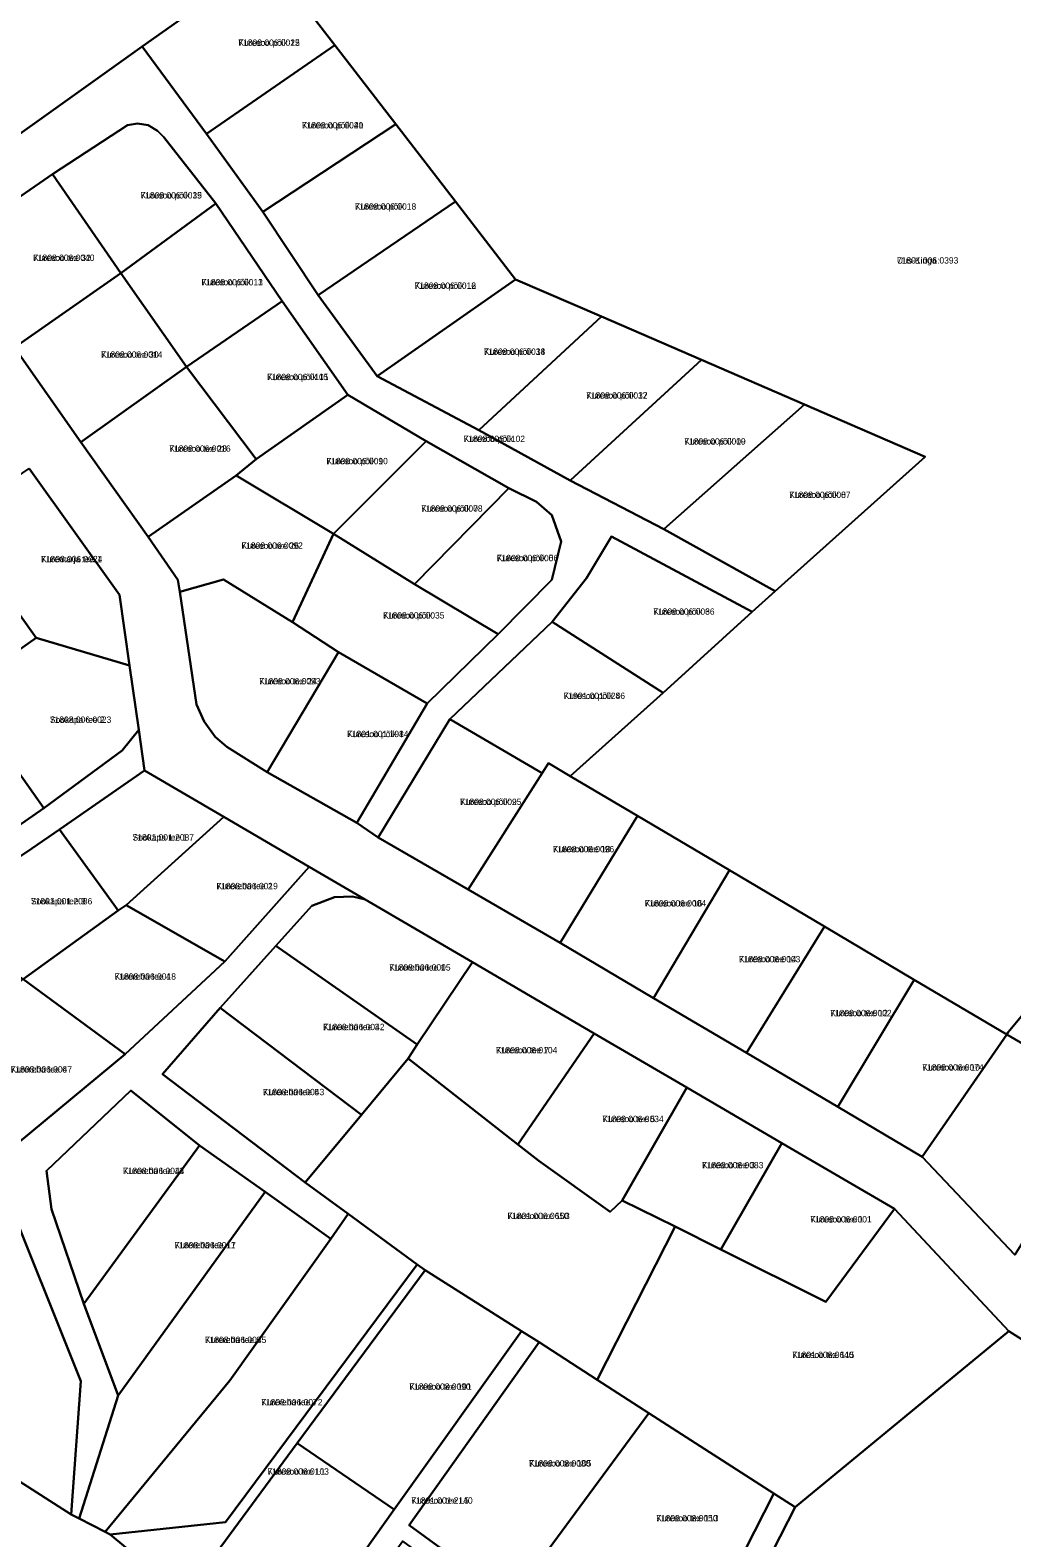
# Model space of a CAD drawing. Extents: x 529768 to 552006, y 6562269 to 6580975.
# Drawn here: x 537239.9 to 537471.9, y 6569320.5 to 6569676.9 of the extents above; entities that cross this region are included whole.
import ezdxf

# ---------------------------------------------------------------- set-up
doc = ezdxf.new("R2010")
doc.units = 0
for name, color, linetype in [('L_AADRESS', 7, 'Continuous'), ('PIIR', 7, 'Continuous'), ('TUNNUS', 7, 'Continuous')]:
    doc.layers.add(name, color=color, linetype=linetype)

msp = doc.modelspace()

# ---------------------------------------------------------------- linework, layer by layer
at = {"layer": 'PIIR'}
for points in [[(537474.6, 6569444.23), (537471.03, 6569440), (537470.72, 6569439.43), (537448.83, 6569452.41), (537427.63, 6569464.97), (537405.17, 6569478.28), (537383.46, 6569491.15), (537367.54, 6569500.54), (537389.48, 6569520.19), (537410.56, 6569539.41), (537415.96, 6569544.24), (537451.44, 6569576.02), (537422.94, 6569588.37), (537398.57, 6569598.92), (537374.91, 6569609.17), (537354.6, 6569617.97), (537340.43, 6569636.35), (537326.34, 6569654.65), (537311.93, 6569673.34), (537296.01, 6569694.01), (537266.4, 6569673.05), (537213.13, 6569635.04)], [(537213.13, 6569635.04), (537266.4, 6569673.05), (537281.57, 6569652.34), (537294.93, 6569633.97), (537308.02, 6569614.26), (537321.92, 6569595.11), (537345.94, 6569582.3), (537367.5, 6569570.41), (537389.64, 6569558.91), (537415.96, 6569544.24), (537410.56, 6569539.41), (537377.33, 6569557.16), (537371.41, 6569547.34), (537363.26, 6569537.01), (537339.1, 6569514.02), (537322.13, 6569486.04), (537317.11, 6569489.53), (537333.75, 6569517.74), (537350.54, 6569534.07), (537363.21, 6569546.91), (537365.44, 6569556.03), (537363.2, 6569562.19), (537359.62, 6569565.4), (537353.04, 6569568.63), (537333.49, 6569579.72), (537314.99, 6569590.68), (537299.48, 6569612.82), (537283.83, 6569635.87), (537271.54, 6569651.62), (537270.01, 6569653.12), (537267.8, 6569654.43), (537265.33, 6569654.78), (537262.93, 6569654.42), (537245.2, 6569642.81), (537219.84, 6569625.32)], [(537236.26, 6569601.86), (537251.93, 6569579.48), (537267.78, 6569557.09), (537274.82, 6569546.97), (537275.33, 6569544.08), (537279.25, 6569517.44), (537281.06, 6569513.47), (537283.63, 6569509.84), (537286.41, 6569507.44), (537295.91, 6569501.5), (537317.11, 6569489.53), (537322.13, 6569486.04), (537343.42, 6569473.73), (537365.15, 6569461.12), (537387.22, 6569448.07), (537409.17, 6569435.09), (537430.8, 6569422.34), (537450.7, 6569410.53), (537472.62, 6569387.4)], [(537523.87, 6569335.93), (537471.2, 6569369.35), (537444.16, 6569398.21), (537417.54, 6569413.78), (537395.1, 6569426.91), (537373.21, 6569439.72), (537344.48, 6569456.52), (537319.09, 6569471.37), (537305.83, 6569479.13), (537285.72, 6569490.91), (537266.97, 6569501.86), (537265.6, 6569511.5), (537263.43, 6569526.68), (537261.05, 6569543.39), (537239.66, 6569573.28)], [(537230.45, 6569408.44), (537262.38, 6569434.81), (537285.95, 6569456.7), (537305.83, 6569479.13), (537319.09, 6569471.37), (537316.1, 6569472.09), (537311.85, 6569471.94), (537306.5, 6569469.84), (537297.98, 6569460.45), (537284.85, 6569445.73), (537271.17, 6569430.09), (537304.9, 6569404.49), (537315.09, 6569397.03), (537310.99, 6569391.17), (537295.49, 6569402.25), (537279.93, 6569413.25), (537263.73, 6569426.21), (537243.81, 6569407.25), (537244.97, 6569398.15), (537252.62, 6569375.8), (537260.69, 6569354.14), (537251.48, 6569325.01), (537249.6, 6569325.97), (537251.88, 6569357.54), (537233.07, 6569404.52)], [(537170.73, 6569376.5), (537249.6, 6569325.97), (537251.48, 6569325.01), (537257.63, 6569321.87), (537258.8, 6569321.28), (537276.4, 6569306.65), (537282.55, 6569275.19), (537226.88, 6569251.23), (537262.82, 6569227.37), (537289.45, 6569209.82), (537323.12, 6569187.65), (537359.8, 6569164.07), (537363.64, 6569147.9), (537368.89, 6569121.58), (537281.43, 6569019.46)]]:
    msp.add_lwpolyline(points, dxfattribs=at)
for points in [[(537266.4, 6569673.05), (537296.01, 6569694.01), (537311.93, 6569673.34), (537281.57, 6569652.34)], [(537281.57, 6569652.34), (537311.93, 6569673.34), (537326.34, 6569654.65), (537294.93, 6569633.97)], [(537262.93, 6569654.42), (537265.33, 6569654.78), (537267.8, 6569654.43), (537270.01, 6569653.12), (537271.54, 6569651.62), (537283.83, 6569635.87), (537261.35, 6569619.4), (537245.2, 6569642.81)], [(537294.93, 6569633.97), (537326.34, 6569654.65), (537340.43, 6569636.35), (537308.02, 6569614.26)], [(537245.2, 6569642.81), (537261.35, 6569619.4), (537236.26, 6569601.86), (537219.84, 6569625.32)], [(537299.48, 6569612.82), (537276.9, 6569597.32), (537261.35, 6569619.4), (537283.83, 6569635.87)], [(537308.02, 6569614.26), (537340.43, 6569636.35), (537354.6, 6569617.97), (537321.92, 6569595.11)], [(537236.26, 6569601.86), (537261.35, 6569619.4), (537276.9, 6569597.32), (537251.93, 6569579.48)], [(537321.92, 6569595.11), (537354.6, 6569617.97), (537374.91, 6569609.17), (537345.94, 6569582.3)], [(537299.48, 6569612.82), (537314.99, 6569590.68), (537293.35, 6569575.49), (537276.9, 6569597.32)], [(537398.57, 6569598.92), (537367.5, 6569570.41), (537345.94, 6569582.3), (537374.91, 6569609.17)], [(537276.9, 6569597.32), (537293.35, 6569575.49), (537288.62, 6569571.63), (537267.78, 6569557.09), (537251.93, 6569579.48)], [(537367.5, 6569570.41), (537398.57, 6569598.92), (537422.94, 6569588.37), (537389.64, 6569558.91)], [(537314.99, 6569590.68), (537333.49, 6569579.72), (537311.65, 6569557.85), (537288.62, 6569571.63), (537293.35, 6569575.49)], [(537389.64, 6569558.91), (537422.94, 6569588.37), (537451.44, 6569576.02), (537415.96, 6569544.24)], [(537333.49, 6569579.72), (537353.04, 6569568.63), (537330.78, 6569545.92), (537311.65, 6569557.85)], [(537239.66, 6569573.28), (537261.05, 6569543.39), (537263.43, 6569526.68), (537241.37, 6569533.21), (537221.56, 6569560.9)], [(537288.62, 6569571.63), (537311.65, 6569557.85), (537301.92, 6569536.92), (537285.59, 6569547), (537275.33, 6569544.08), (537274.82, 6569546.97), (537267.78, 6569557.09)], [(537353.04, 6569568.63), (537359.62, 6569565.4), (537363.2, 6569562.19), (537365.44, 6569556.03), (537363.21, 6569546.91), (537350.54, 6569534.07), (537330.78, 6569545.92)], [(537241.37, 6569533.21), (537223.58, 6569520.73), (537204.1, 6569548.53), (537221.56, 6569560.9)], [(537311.65, 6569557.85), (537330.78, 6569545.92), (537350.54, 6569534.07), (537333.75, 6569517.74), (537312.76, 6569529.87), (537301.92, 6569536.92)], [(537410.56, 6569539.41), (537389.48, 6569520.19), (537363.26, 6569537.01), (537371.41, 6569547.34), (537377.33, 6569557.16)], [(537285.59, 6569547), (537301.92, 6569536.92), (537312.76, 6569529.87), (537295.91, 6569501.5), (537286.41, 6569507.44), (537283.63, 6569509.84), (537281.06, 6569513.47), (537279.25, 6569517.44), (537275.33, 6569544.08)], [(537362.39, 6569503.59), (537360.9, 6569501.26), (537339.1, 6569514.02), (537363.26, 6569537.01), (537389.48, 6569520.19), (537367.54, 6569500.54)], [(537241.37, 6569533.21), (537263.43, 6569526.68), (537265.6, 6569511.5), (537261.64, 6569506.58), (537243.17, 6569492.95), (537223.58, 6569520.73)], [(537295.91, 6569501.5), (537312.76, 6569529.87), (537333.75, 6569517.74), (537317.11, 6569489.53)], [(537223.58, 6569520.73), (537243.17, 6569492.95), (537225.98, 6569481.04), (537206.6, 6569508.71)], [(537265.6, 6569511.5), (537266.97, 6569501.86), (537246.86, 6569487.92), (537240.36, 6569483.41), (537217.2, 6569467.96), (537196.48, 6569452.42), (537171.01, 6569434.5), (537144.46, 6569415.89), (537140.89, 6569420.64), (537157.77, 6569433.15), (537174.98, 6569445.45), (537192.58, 6569456.86), (537212.1, 6569471.37), (537225.98, 6569481.04), (537243.17, 6569492.95), (537261.64, 6569506.58)], [(537322.13, 6569486.04), (537339.1, 6569514.02), (537360.9, 6569501.26), (537343.42, 6569473.73)], [(537470.72, 6569439.43), (537471.03, 6569440), (537474.6, 6569444.23), (537515.68, 6569419.92), (537527.29, 6569439.41), (537538.02, 6569457.44), (537550.64, 6569478.65), (537543.58, 6569482.7), (537558.09, 6569507.89), (537568.78, 6569497.06), (537554.51, 6569473.16), (537543.21, 6569454.47), (537532.42, 6569436.52), (537520.93, 6569416.97), (537556.5, 6569395.83), (537552.48, 6569389.3), (537548.03, 6569393.84), (537533.88, 6569402.34), (537515.22, 6569413.37), (537495.89, 6569424.8)], [(537260.69, 6569468.76), (537246.86, 6569487.92), (537266.97, 6569501.86), (537285.72, 6569490.91), (537262.63, 6569470.04)], [(537362.39, 6569503.59), (537367.54, 6569500.54), (537383.46, 6569491.15), (537365.15, 6569461.12), (537343.42, 6569473.73), (537360.9, 6569501.26)], [(537305.83, 6569479.13), (537285.95, 6569456.7), (537262.63, 6569470.04), (537285.72, 6569490.91)], [(537387.22, 6569448.07), (537365.15, 6569461.12), (537383.46, 6569491.15), (537405.17, 6569478.28)], [(537238.31, 6569452.5), (537217.2, 6569467.96), (537240.36, 6569483.41), (537246.86, 6569487.92), (537260.69, 6569468.76)], [(537409.17, 6569435.09), (537387.22, 6569448.07), (537405.17, 6569478.28), (537427.63, 6569464.97)], [(537344.48, 6569456.52), (537331.41, 6569437.06), (537297.98, 6569460.45), (537306.5, 6569469.84), (537311.85, 6569471.94), (537316.1, 6569472.09), (537319.09, 6569471.37)], [(537262.63, 6569470.04), (537285.95, 6569456.7), (537262.38, 6569434.81), (537238.31, 6569452.5), (537260.69, 6569468.76)], [(537427.63, 6569464.97), (537448.83, 6569452.41), (537430.8, 6569422.34), (537409.17, 6569435.09)], [(537331.41, 6569437.06), (537329.24, 6569433.8), (537318.2, 6569420.5), (537284.85, 6569445.73), (537297.98, 6569460.45)], [(537344.48, 6569456.52), (537373.21, 6569439.72), (537355.16, 6569413.49), (537329.24, 6569433.8), (537331.41, 6569437.06)], [(537262.38, 6569434.81), (537230.45, 6569408.44), (537211.62, 6569432.95), (537238.31, 6569452.5)], [(537470.72, 6569439.43), (537450.7, 6569410.53), (537430.8, 6569422.34), (537448.83, 6569452.41)], [(537318.2, 6569420.5), (537304.9, 6569404.49), (537271.17, 6569430.09), (537284.85, 6569445.73)], [(537373.21, 6569439.72), (537395.1, 6569426.91), (537379.85, 6569400.18), (537376.96, 6569397.57), (537360.17, 6569409.56), (537355.16, 6569413.49)], [(537495.89, 6569424.8), (537472.62, 6569387.4), (537450.7, 6569410.53), (537470.72, 6569439.43)], [(537329.24, 6569433.8), (537355.16, 6569413.49), (537360.17, 6569409.56), (537376.96, 6569397.57), (537379.85, 6569400.18), (537392.33, 6569394.03), (537373.92, 6569357.84), (537360.2, 6569366.7), (537356.02, 6569369.35), (537333.24, 6569383.74), (537331.41, 6569385.08), (537315.09, 6569397.03), (537304.9, 6569404.49), (537318.2, 6569420.5)], [(537279.93, 6569413.25), (537252.62, 6569375.8), (537244.97, 6569398.15), (537243.81, 6569407.25), (537263.73, 6569426.21)], [(537395.1, 6569426.91), (537417.54, 6569413.78), (537403.13, 6569388.64), (537392.33, 6569394.03), (537379.85, 6569400.18)], [(537279.93, 6569413.25), (537295.49, 6569402.25), (537260.69, 6569354.14), (537252.62, 6569375.8)], [(537417.54, 6569413.78), (537444.16, 6569398.21), (537427.97, 6569376.25), (537403.13, 6569388.64)], [(537251.88, 6569357.54), (537249.6, 6569325.97), (537170.73, 6569376.5), (537203.24, 6569392.77), (537233.07, 6569404.52)], [(537310.99, 6569391.17), (537287.09, 6569357.63), (537257.63, 6569321.87), (537251.48, 6569325.01), (537260.69, 6569354.14), (537295.49, 6569402.25)], [(537373.92, 6569357.84), (537392.33, 6569394.03), (537403.13, 6569388.64), (537427.97, 6569376.25), (537444.16, 6569398.21), (537471.2, 6569369.35), (537420.72, 6569327.75), (537415.64, 6569330.96), (537386.16, 6569349.94)], [(537258.8, 6569321.28), (537257.63, 6569321.87), (537287.09, 6569357.63), (537310.99, 6569391.17), (537315.09, 6569397.03), (537331.41, 6569385.08), (537286.07, 6569324.15)], [(537331.41, 6569385.08), (537333.24, 6569383.74), (537303.05, 6569342.82), (537276.4, 6569306.65), (537258.8, 6569321.28), (537286.07, 6569324.15)], [(537303.05, 6569342.82), (537333.24, 6569383.74), (537356.02, 6569369.35), (537325.92, 6569327.15)], [(537356.02, 6569369.35), (537360.2, 6569366.7), (537329.49, 6569323.5), (537353.94, 6569305.69), (537351.65, 6569302.39), (537327.98, 6569319.65), (537304.66, 6569286.98), (537299.8, 6569290.36), (537325.92, 6569327.15)], [(537392.4, 6569272.37), (537420.72, 6569327.75), (537471.2, 6569369.35), (537523.87, 6569335.93), (537456.97, 6569225.74), (537428.48, 6569246.54)], [(537329.49, 6569323.5), (537360.2, 6569366.7), (537373.92, 6569357.84), (537386.16, 6569349.94), (537360.1, 6569314.6), (537353.94, 6569305.69)], [(537386.16, 6569349.94), (537415.64, 6569330.96), (537397.29, 6569294.89), (537360.1, 6569314.6)], [(537325.92, 6569327.15), (537299.8, 6569290.36), (537276.4, 6569306.65), (537303.05, 6569342.82)], [(537370.36, 6569241.96), (537383.8, 6569268.29), (537397.29, 6569294.89), (537415.64, 6569330.96), (537420.72, 6569327.75), (537392.4, 6569272.37), (537375.53, 6569238.29)]]:
    msp.add_lwpolyline(points, close=True, dxfattribs=at)

# ---------------------------------------------------------------- texts
at = {"layer": 'L_AADRESS'}
for s, p in [('Kuresoo põik 22', (537289.13, 6569673.18)), ('Kuresoo põik 20', (537304.15, 6569653.65)), ('Kuresoo põik 15', (537266.01, 6569637.09)), ('Kuresoo põik 18', (537316.66, 6569634.46)), ('Kuresoo tee 32', (537240.63, 6569622.33)), ('Uus-Kinga', (537444.76, 6569621.71)), ('Kuresoo põik 13', (537280.41, 6569616.55)), ('Kuresoo põik 16', (537330.79, 6569615.73)), ('Kuresoo tee 30', (537256.68, 6569599.44)), ('Kuresoo põik 14', (537347.14, 6569600.13)), ('Kuresoo põik 11', (537295.92, 6569594.15)), ('Kuresoo põik 12', (537371.32, 6569589.79)), ('Kuresoo põik', (537342.37, 6569579.54)), ('Kuresoo põik 10', (537394.51, 6569578.92)), ('Kuresoo tee 28', (537272.8, 6569577.21)), ('Kuresoo põik 9', (537309.95, 6569574.27)), ('Kuresoo põik 7', (537332.34, 6569563.05)), ('Kuresoo põik 8', (537419.3, 6569566.3)), ('Kuresoo tee 26', (537289.86, 6569554.28)), ('Kuremarja tee 1', (537242.5, 6569551.1)), ('Kuresoo põik 5', (537350.2, 6569551.35)), ('Kuresoo põik 6', (537387.16, 6569538.68)), ('Kuresoo põik 3', (537323.33, 6569537.79)), ('Kuresoo tee 24', (537294.04, 6569522.22)), ('Kuresoo põik 4', (537366, 6569518.78)), ('Sookäpa tee 2', (537244.59, 6569513.13)), ('Kuresoo põik 1', (537314.83, 6569509.75)), ('Kuresoo põik 2', (537341.52, 6569493.72)), ('Sookäpa tee 1', (537264.13, 6569485.31)), ('Kuresoo tee 18', (537363.44, 6569482.54)), ('Kurereha tee 2', (537283.95, 6569473.8)), ('Sookäpa tee 3', (537240.11, 6569470.21)), ('Kuresoo tee 16', (537385.16, 6569469.72)), ('Kuresoo tee 14', (537407.43, 6569456.53)), ('Kurereha tee 1', (537324.78, 6569454.57)), ('Kurereha tee 4', (537259.88, 6569452.42)), ('Kuresoo tee 12', (537429, 6569443.78)), ('Kurereha tee 3', (537309.16, 6569440.48)), ('Kuresoo tee 7', (537350, 6569435)), ('Kurereha tee 6', (537235.33, 6569430.47)), ('Kuresoo tee 10', (537450.76, 6569430.94)), ('Kurereha tee 5', (537294.92, 6569425.11)), ('Kuresoo tee 5', (537375.13, 6569418.74)), ('Kurereha tee 13', (537261.87, 6569406.46)), ('Kuresoo tee 3', (537398.7, 6569407.83)), ('Kuresoo tee 103', (537352.72, 6569395.82)), ('Kuresoo tee 1', (537424.29, 6569395.02)), ('Kurereha tee 11', (537274.05, 6569388.91)), ('Kurereha tee 9', (537281.23, 6569366.53)), ('Kuresoo tee 115', (537420, 6569362.98)), ('Kuresoo tee 101', (537329.54, 6569355.47)), ('Kurereha tee 7', (537294.52, 6569351.78)), ('Kuresoo tee L1', (537296.02, 6569335.4)), ('Kuresoo tee 105', (537357.82, 6569337.33)), ('Kuresoo tee L5', (537330, 6569328.54)), ('Kuresoo tee 113', (537387.87, 6569324.36))]:
    msp.add_text(s, height=1.5, dxfattribs=at).set_placement(p)
at = {"layer": 'TUNNUS'}
for s, p in [('71808:006:0015', (537289.13, 6569673.18)), ('71808:006:0041', (537304.15, 6569653.65)), ('71808:006:0039', (537266.01, 6569637.09)), ('71808:006:0013', (537316.66, 6569634.46)), ('71808:006:0040', (537240.63, 6569622.33)), ('71801:006:0393', (537444.76, 6569621.71)), ('71808:006:0011', (537280.41, 6569616.55)), ('71808:006:0012', (537330.79, 6569615.73)), ('71808:006:0014', (537256.68, 6569599.44)), ('71808:006:0038', (537347.14, 6569600.13)), ('71808:006:0105', (537295.92, 6569594.15)), ('71808:006:0037', (537371.32, 6569589.79)), ('71808:006:0102', (537342.37, 6569579.54)), ('71808:006:0009', (537394.51, 6569578.92)), ('71808:006:0016', (537272.8, 6569577.21)), ('71808:006:0010', (537309.95, 6569574.27)), ('71808:006:0008', (537332.34, 6569563.05)), ('71808:006:0007', (537419.3, 6569566.3)), ('71808:006:0092', (537289.86, 6569554.28)), ('71808:006:0024', (537242.5, 6569551.1)), ('71808:006:0006', (537350.2, 6569551.35)), ('71808:006:0036', (537387.16, 6569538.68)), ('71808:006:0035', (537323.33, 6569537.79)), ('71808:006:0093', (537294.04, 6569522.22)), ('71901:001:0286', (537366, 6569518.78)), ('71808:006:0023', (537244.59, 6569513.13)), ('71801:001:1984', (537314.83, 6569509.75)), ('71808:006:0095', (537341.52, 6569493.72)), ('71801:001:2087', (537264.13, 6569485.31)), ('71808:006:0096', (537363.44, 6569482.54)), ('71808:006:0019', (537283.95, 6569473.8)), ('71801:001:2086', (537240.11, 6569470.21)), ('71808:006:0004', (537385.16, 6569469.72)), ('71808:006:0003', (537407.43, 6569456.53)), ('71808:006:0005', (537324.78, 6569454.57)), ('71808:006:0018', (537259.88, 6569452.42)), ('71808:006:0002', (537429, 6569443.78)), ('71808:006:0042', (537309.16, 6569440.48)), ('71808:006:0104', (537350, 6569435)), ('71808:006:0047', (537235.33, 6569430.47)), ('71808:006:0074', (537450.76, 6569430.94)), ('71808:006:0043', (537294.92, 6569425.11)), ('71808:006:0034', (537375.13, 6569418.74)), ('71808:006:0044', (537261.87, 6569406.46)), ('71808:006:0083', (537398.7, 6569407.83)), ('71801:006:0650', (537352.72, 6569395.82)), ('71808:006:0001', (537424.29, 6569395.02)), ('71808:006:0017', (537274.05, 6569388.91)), ('71808:006:0045', (537281.23, 6569366.53)), ('71801:006:0640', (537420, 6569362.98)), ('71808:008:0090', (537329.54, 6569355.47)), ('71808:006:0072', (537294.52, 6569351.78)), ('71808:006:0103', (537296.02, 6569335.4)), ('71808:008:0080', (537357.82, 6569337.33)), ('71801:001:2140', (537330, 6569328.54)), ('71808:008:0050', (537387.87, 6569324.36))]:
    msp.add_text(s, height=1.5, dxfattribs=at).set_placement(p)

doc.saveas('drawing.dxf')
